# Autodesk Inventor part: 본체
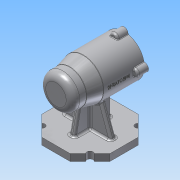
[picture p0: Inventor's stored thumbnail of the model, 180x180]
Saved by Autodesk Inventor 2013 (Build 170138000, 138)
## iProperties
Created: 2021-01
Part Number: 본체
Material: 알루미늄 6061
Document SubType Name: Modeling
Designer: Administrator
Density: 2.71 g/cm^3
Mass: 632.479 g
Surface Area: 614.545 cm^2
Volume: 233.387 cm^3
Author: Administrator
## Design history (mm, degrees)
sketch "스케치1" dims "d0" = 100
  geometry: L1 (20.711, 50)-(50, 20.711); L2 (50, 20.711)-(50, -20.711); L3 (50, -20.711)-(20.711, -50); L4 (20.711, -50)-(-20.711, -50); L5 (-20.711, -50)-(-50, -20.711); L6 (-50, -20.711)-(-50, 20.711); L7 (-50, 20.711)-(-20.711, 50); L8 (-20.711, 50)-(20.711, 50); 4 further points
  constraints: 16 end point, 2 coincident, 2 vertical alignment, 1 midpoint, 19 other
extrude "돌출1" new body sketch "스케치1" distance "d2" = 10; taper "d3" = 0 deg
sketch "스케치2"
  geometry: L1 (50, 75)-(-50, 75); L2 (-20.711, 0)-(20.711, 0) reference; L3 (-10, 105)-(-30, 100); L4 (-30, 100)-(-40, 100); L5 (-50, 90)-(-50, 75); L6 (-10, 105)-(50, 105); L7 (50, 105)-(50, 75); A1 r 10 centre (-40, 90) between (-40, 100) and (-50, 90); 2 further points
  constraints: 12 end point, 2 point on circle, 2 tangent, 2 vertical, 1 centre point, 1 horizontal, 1 perpendicular, 1 vertical alignment
  dimensions: "d4" = 75 distance between parallel lines of L2 L1; "d5" = 100 distance of L1.start L1.end; "d7" = 20 distance from line of L3.end L5; "d8" = 40 distance from line of L3.start L5; "d9" = 50 diameter of L4 L1; "d10" = 60 diameter of L6 L1; "d11" = 10 radius of A1
revolve "회전1" sketch "스케치2" stored, may be unused: angle "d12" = 90 deg
sketch "스케치3"
  geometry: L1 (50, 45)-(50, 105) reference; L2 (-20.711, 0)-(20.711, 0) reference; L3 (-0.939, 98.948)-(-0.939, 98.601); L4 (-50, 60)-(-50, 90) reference; L5 (50, 75)-(-50, 75); L6 (50, 96)-(35, 96); L7 (35, 96)-(35, 99); L8 (35, 99)-(-7, 99); L9 (-7, 99)-(-7, 96); L10 (-7, 96)-(-19, 96); L11 (-19, 96)-(-19, 92.5); L12 (-19, 92.5)-(-37, 92.5); L13 (-37, 92.5)-(-37, 91); L14 (-37, 91)-(-41, 91); L15 (-41, 91)-(-41, 85.5); L16 (-41, 85.5)-(-41, 85.5); L17 (-44, 82.5)-(-44, 75); A1 r 3 centre (-41, 82.5) between (-41, 85.5) and (-44, 82.5); 2 further points
  constraints: 28 end point, 7 perpendicular, 5 parallel, 4 point on line, 2 midpoint, 2 point on circle, 2 tangent, 1 centre point
  dimensions: "d15" = 15 distance of L6.start L6.end; "d17" = 42 distance of L7.end L8.end; "d18" = 12 distance of L9.end L10.end; "d19" = 18 distance of L11.end L12.end; "d20" = 4 distance of L13.end L14.end; "d21" = 3 distance of L15.end point (-44, 85.5); "d22" = 42 diameter of L6 L5; "d23" = 48 diameter of L8 L5; "d24" = 42 diameter of L10 L5; "d25" = 35 diameter of L12 L5; "d26" = 32 diameter of L14 L5; "d27" = 21 diameter of L16 L5; "d28" = 3 radius of A1
revolve "회전2" sketch "스케치3" stored, may be unused: angle "d29" = 90 deg
sketch "스케치4"
  geometry: L1 (-30, 50)-(-10, 45) reference; L2 (-20.711, 10)-(-50, 10) reference; L3 (20.711, 10)-(-20.711, 10) reference; L4 (50, 10)-(20.711, 10) reference; L5 (-10, 45)-(50, 45) reference; L6 (-19.27, 49.77)-(-27, 10); L7 (-19.27, 49.77)-(27, 49.77); L8 (27, 49.77)-(27, 10); 1 further point
  constraints: 6 end point, 2 point on line, 1 parallel, 1 perpendicular
  dimensions: "d30" = 101 deg angle of L2 L6; "d31" = 23 distance of L2.end L6.end; "d32" = 23 distance of L4.start L8.end; "d99" = 46.2695 distance of L6.start L7.end
extrude "돌출2" join sketch "스케치4" stored distance "d34" = 8; taper "d35" = 0 deg
sketch "스케치5"
  geometry: L1 (20.711, 10)-(-20.711, 10) reference; L2 (-20.711, 10)-(-50, 10) reference; L3 (50, 10)-(20.711, 10) reference; L4 (-19.606, 52.293)-(-35, 10); L5 (19.606, 52.293)-(35, 10); A1 r 30 centre (0, 75) between (4, 45.268) and (-4, 45.268) reference; 1 further point
  constraints: 4 end point, 2 point on circle, 2 point on line
  dimensions: "d37" = 15 distance of L2.end L4.end; "d38" = 110 deg angle of L2 L4; "d45" = 15 distance of L3.start L5.end; "d46" = 110 deg angle of L3 L5
feature "리브1" dims "d39" = 1, "d40" = 8, "d41" = 0, "d42" = 0, "d43" = 1, "d44" = 1
feature "리브2" dims "d47" = 1, "d48" = 8, "d49" = 0, "d50" = 0, "d51" = 1, "d52" = 1
sketch "스케치6"
  geometry: L1 (0, 0)-(0, 50); L2 (0, 0)-(-35.355, 35.355); L3 (0, 0)-(35.355, 35.355); L4 (0, 0)-(-42.323, -42.323); L5 (0, 0)-(46.839, -46.839); L6 (0, 0)-(0, -67.844); L7 (-20.711, -50)-(-50, -20.711) reference; L8 (50, -20.711)-(20.711, -50) reference; C1 r 4.5 at (-35.355, 35.355); C2 r 4.5 at (35.355, 35.355); C3 r 4.5 at (-35.355, -35.355); C4 r 4.5 at (35.355, -35.355); A1 r 50 centre (0, 0) between (0, 50) and (-35.355, 35.355); 1 further point
  constraints: 12 end point, 5 centre point, 3 coincident, 3 point on circle, 2 collinear, 2 midpoint, 1 horizontal alignment, 1 vertical
  dimensions: "d53" = 100 diameter of A1; "d56" = 45 deg angle of L1 L2; "d58" = 45 deg angle of L3 L1; "d60" = 9 diameter of C1; "d61" = 9 diameter of C2; "d62" = 45 deg angle of L6 L5; "d63" = 9 diameter of C3; "d64" = 9 diameter of C4
extrude "돌출3" cut sketch "스케치6" stored distance "d65" = 8; taper "d66" = 0 deg
sketch "스케치8"
  geometry: A1 r 30 centre (0, 0) between (-4, 29.732) and (4, 29.732) reference; A2 r 6 centre (0, -30) between (-5.97, -29.4) and (5.97, -29.4); A3 r 6 centre (-30, 0) between (-29.4, 5.97) and (-29.4, -5.97); A4 r 6 centre (30, 0) between (29.4, -5.97) and (29.4, 5.97); A5 r 6 centre (0, 30) between (5.97, 29.4) and (-5.97, 29.4); 6 further points
  constraints: 12 point on circle, 4 centre point, 4 coincident, 2 horizontal alignment, 2 vertical alignment, 12 other
  dimensions: "d69" = 12 diameter of A2; "d71" = 12 diameter of A4; "d72" = 12 diameter of A3; "d73" = 12 diameter of A5
extrude "돌출4" join sketch "스케치8" distance "d74" = 16; taper "d75" = 0 deg
sketch "스케치9"
  geometry: C1 r 21 at (0, -30) reference; 2 further points
  constraints: 1 vertical alignment
  dimensions: "d78" = 30 distance of C1.centre point (0, -60)
hole "구멍1" sketch "스케치9" at (0, -60) diameter "d79" = 3.242; stored, may be unused: countersink angle "d83" = 90 deg, drill point angle "d85" = 118 deg; dims "d80" = 8, "d81" = 4, "d82" = 2, "d84" = 10
node "작업 평면3"
sketch "스케치12"
  geometry: L1 (30, 29.4)-(30, 36) reference; L2 (30, -6)-(30, 6) reference; 5 further points
  constraints: 1 horizontal alignment, 1 midpoint, 1 other
  dimensions: "d89" = 38 distance from line of L1 point (-8, 0)
feature "엠보싱1" sketch "스케치12" dims "d4" = 75, "d5" = 100, "d7" = 20, "d8" = 40, "d9" = 50, "d10" = 60, "d11" = 10, "d90" = 0.5, "d91" = 0
fillet "모깎기1" dims "d92" = 3
fillet "모깎기2" dims "d93" = 3
fillet "모깎기3" dims "d94" = 3
fillet "모깎기4" dims "d95" = 3, "d96" = 0.3
fillet "모깎기5" dims "d97" = 3
fillet "모깎기6" dims "d98" = 1
node "솔리드1"
pattern_circular "원형 패턴1" dims angle "d87" = 360 deg
